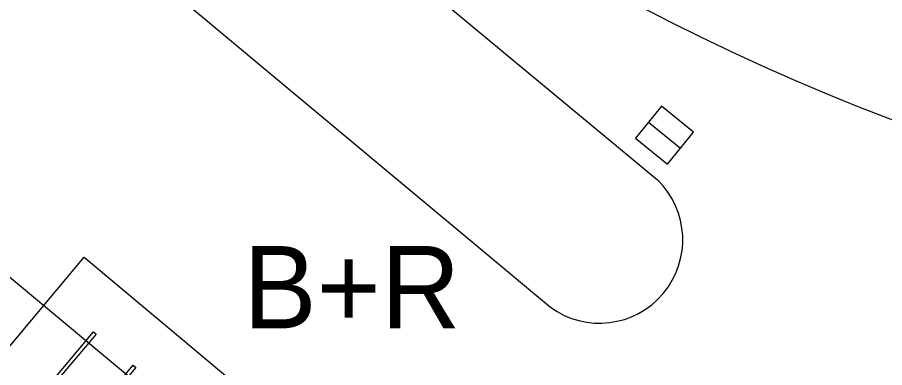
# Model space of a CAD drawing. Extents: x -438200 to -437954, y -1133133 to -1132850.
# Drawn here: x -438078.37 to -438067.83, y -1132980.73 to -1132976.48 of the extents above; entities that cross this region are included whole.
import ezdxf

# ---------------------------------------------------------------- set-up
doc = ezdxf.new("R2010")
doc.units = 0
for name, color, linetype in [('Default', 7, 'Continuous'), ('MOBILIÁŘ', 7, 'Continuous'), ('Vrstva 1', 7, 'Continuous'), ('Vrstva 10', 7, 'Continuous'), ('Vrstva 27', 7, 'Continuous')]:
    doc.layers.add(name, color=color, linetype=linetype)

# ---------------------------------------------------------------- blocks, each defined once
blk = doc.blocks.new('A$C73EC33FB')
at = {"layer": 'Default'}
for points in [[(-39000, 25012), (0, 25012), (0, 0), (-39000, 0)], [(-32310, 18759), (-31900, 18759), (-31900, 9105), (-32310, 9105)], [(-26014, 18759), (-25605, 18759), (-25605, 9105), (-26014, 9105)], [(-19705, 18759), (-19295, 18759), (-19295, 9105), (-19705, 9105)], [(-13409, 18759), (-13000, 18759), (-13000, 9105), (-13409, 9105)], [(-7100, 18759), (-6690, 18759), (-6690, 9105), (-7100, 9105)]]:
    blk.add_lwpolyline(points, close=True, dxfattribs=at)

msp = doc.modelspace()

# ---------------------------------------------------------------- linework, layer by layer
at = {"layer": 'Vrstva 1'}
for p, q in [((-438070.505, -1132977.911), (-438070.505, -1132977.911)), ((-438070.59, -1132978.455), (-438070.59, -1132978.455)), ((-438070.486, -1132979.79), (-438070.486, -1132979.79)), ((-438071.892, -1132980), (-438071.892, -1132980))]:
    msp.add_line(p, q, dxfattribs=at)
msp.add_arc((-438057.962, -1132951.913), 27.6, 199.5386, 254.3601, dxfattribs=at)
msp.add_arc((-438057.962, -1132951.913), 27.6, 199.5386, 254.3601, dxfattribs=at)
at = {"layer": 'Vrstva 10'}
for points in [[(-438086.926, -1132964.916), (-438070.59, -1132978.455)], [(-438088.082, -1132966.508), (-438071.892, -1132980)], [(-438091.201, -1132969.023), (-438075.155, -1132982.388)]]:
    msp.add_lwpolyline(points, dxfattribs=at)
msp.add_arc((-438071.296, -1132979.182), 1.013, 233.9189, 45.8381, dxfattribs=at)
at = {"layer": 'Vrstva 27'}
msp.add_line((-438070.699, -1132977.753), (-438070.311, -1132978.069), dxfattribs=at)
msp.add_lwpolyline([(-438070.857, -1132977.946), (-438070.47, -1132978.263), (-438070.153, -1132977.876), (-438070.54, -1132977.559)], close=True, dxfattribs=at)

# ---------------------------------------------------------------- block references
at = {"layer": 'MOBILIÁŘ', "xscale": 0.0001, "yscale": 9.999999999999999e-05, "rotation": -39.966187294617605}
msp.add_blockref('A$C73EC33FB', (-438076.175, -1132983.814), dxfattribs=at)
msp.add_blockref('A$C73EC33FB', (-438076.175, -1132983.814), dxfattribs=at)

# ---------------------------------------------------------------- texts
at = {"layer": 'Vrstva 1'}
msp.add_text('B+R', height=1, dxfattribs=at).set_placement((-438075.625, -1132980.257))
msp.add_text('B+R', height=1, dxfattribs=at).set_placement((-438075.625, -1132980.257))

doc.saveas('drawing.dxf')
